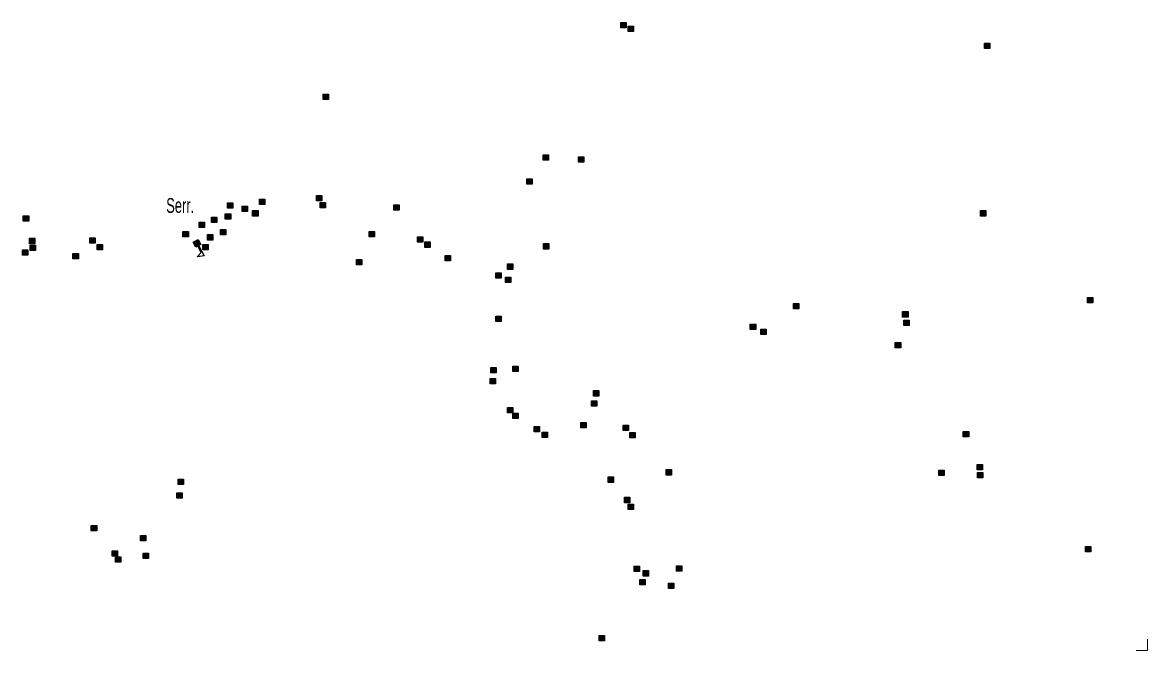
# Model space of a CAD drawing. Extents: x 647.8 to 672.9, y 6929.3 to 6957.3.
# Drawn here: x 666.42 to 672.48, y 6929.25 to 6932.64 of the extents above; entities that cross this region are included whole.
import ezdxf
from ezdxf.enums import TextEntityAlignment as Align

# ---------------------------------------------------------------- set-up
doc = ezdxf.new("R2010")
doc.units = 0
doc.header["$LTSCALE"] = 0.032
for name, color, linetype, lineweight in [('2', 7, 'Continuous', 25), ('4', 7, 'Continuous', 25), ('63', 7, 'Continuous', 13)]:
    doc.layers.add(name, color=color, linetype=linetype, lineweight=lineweight)
doc.layers.add('61', color=7, linetype='Continuous')

msp = doc.modelspace()

# ---------------------------------------------------------------- hatches: boundary and pattern name
at = {"layer": '2'}
for points in [[(669.6418, 6932.6371), (669.6708, 6932.6371), (669.6708, 6932.6081), (669.6418, 6932.6081)], [(669.6813, 6932.6174), (669.7103, 6932.6174), (669.7103, 6932.5884), (669.6813, 6932.5884)], [(671.6009, 6932.5252), (671.6299, 6932.5252), (671.6299, 6932.4962), (671.6009, 6932.4962)], [(668.0381, 6932.251), (668.0671, 6932.251), (668.0671, 6932.222), (668.0381, 6932.222)], [(669.2228, 6931.9241), (669.2518, 6931.9241), (669.2518, 6931.8951), (669.2228, 6931.8951)], [(669.4137, 6931.9131), (669.4427, 6931.9131), (669.4427, 6931.8841), (669.4137, 6931.8841)], [(669.135, 6931.7947), (669.164, 6931.7947), (669.164, 6931.7657), (669.135, 6931.7657)], [(668.003, 6931.7047), (668.032, 6931.7047), (668.032, 6931.6757), (668.003, 6931.6757)], [(667.5226, 6931.6652), (667.5516, 6931.6652), (667.5516, 6931.6362), (667.5226, 6931.6362)], [(667.6015, 6931.6477), (667.6305, 6931.6477), (667.6305, 6931.6187), (667.6015, 6931.6187)], [(667.6959, 6931.685), (667.7249, 6931.685), (667.7249, 6931.656), (667.6959, 6931.656)], [(668.0228, 6931.6674), (668.0518, 6931.6674), (668.0518, 6931.6384), (668.0228, 6931.6384)], [(668.4198, 6931.6543), (668.4488, 6931.6543), (668.4488, 6931.6253), (668.4198, 6931.6253)], [(666.4234, 6931.595), (666.4524, 6931.595), (666.4524, 6931.566), (666.4234, 6931.566)], [(667.437, 6931.5884), (667.466, 6931.5884), (667.466, 6931.5594), (667.437, 6931.5594)], [(667.5116, 6931.606), (667.5406, 6931.606), (667.5406, 6931.577), (667.5116, 6931.577)], [(667.6586, 6931.6235), (667.6876, 6931.6235), (667.6876, 6931.5945), (667.6586, 6931.5945)], [(671.579, 6931.6235), (671.608, 6931.6235), (671.608, 6931.5945), (671.579, 6931.5945)], [(667.2834, 6931.5117), (667.3124, 6931.5117), (667.3124, 6931.4827), (667.2834, 6931.4827)], [(667.3712, 6931.5621), (667.4002, 6931.5621), (667.4002, 6931.5331), (667.3712, 6931.5331)], [(667.485, 6931.5214), (667.514, 6931.5214), (667.514, 6931.4924), (667.485, 6931.4924)], [(668.286, 6931.5117), (668.315, 6931.5117), (668.315, 6931.4827), (668.286, 6931.4827)], [(666.4564, 6931.4744), (666.4854, 6931.4744), (666.4854, 6931.4454), (666.4564, 6931.4454)], [(666.781, 6931.4766), (666.81, 6931.4766), (666.81, 6931.4476), (666.781, 6931.4476)], [(667.4151, 6931.4941), (667.4441, 6931.4941), (667.4441, 6931.4651), (667.4151, 6931.4651)], [(668.5471, 6931.4831), (668.5761, 6931.4831), (668.5761, 6931.4541), (668.5471, 6931.4541)], [(668.5866, 6931.4546), (668.6156, 6931.4546), (668.6156, 6931.4256), (668.5866, 6931.4256)], [(666.4191, 6931.4129), (666.4481, 6931.4129), (666.4481, 6931.3839), (666.4191, 6931.3839)], [(666.4607, 6931.4371), (666.4897, 6931.4371), (666.4897, 6931.4081), (666.4607, 6931.4081)], [(666.6911, 6931.3932), (666.7201, 6931.3932), (666.7201, 6931.3642), (666.6911, 6931.3642)], [(666.8205, 6931.4415), (666.8495, 6931.4415), (666.8495, 6931.4125), (666.8205, 6931.4125)], [(667.3909, 6931.4415), (667.4199, 6931.4415), (667.4199, 6931.4125), (667.3909, 6931.4125)], [(669.225, 6931.4458), (669.254, 6931.4458), (669.254, 6931.4168), (669.225, 6931.4168)], [(668.218, 6931.3603), (668.247, 6931.3603), (668.247, 6931.3313), (668.218, 6931.3313)], [(668.6963, 6931.3822), (668.7253, 6931.3822), (668.7253, 6931.3532), (668.6963, 6931.3532)], [(669.0319, 6931.3361), (669.0609, 6931.3361), (669.0609, 6931.3071), (669.0319, 6931.3071)], [(668.9683, 6931.2879), (668.9973, 6931.2879), (668.9973, 6931.2589), (668.9683, 6931.2589)], [(669.021, 6931.2659), (669.05, 6931.2659), (669.05, 6931.2369), (669.021, 6931.2369)], [(672.156, 6931.1563), (672.185, 6931.1563), (672.185, 6931.1273), (672.156, 6931.1273)], [(670.572, 6931.1233), (670.601, 6931.1233), (670.601, 6931.0943), (670.572, 6931.0943)], [(668.9683, 6931.0553), (668.9973, 6931.0553), (668.9973, 6931.0263), (668.9683, 6931.0263)], [(671.16, 6931.0795), (671.189, 6931.0795), (671.189, 6931.0505), (671.16, 6931.0505)], [(671.1665, 6931.0334), (671.1955, 6931.0334), (671.1955, 6931.0044), (671.1665, 6931.0044)], [(670.3395, 6931.0115), (670.3685, 6931.0115), (670.3685, 6930.9825), (670.3395, 6930.9825)], [(670.3965, 6930.9851), (670.4255, 6930.9851), (670.4255, 6930.9561), (670.3965, 6930.9561)], [(671.1205, 6930.9127), (671.1495, 6930.9127), (671.1495, 6930.8837), (671.1205, 6930.8837)], [(669.0604, 6930.7855), (669.0894, 6930.7855), (669.0894, 6930.7565), (669.0604, 6930.7565)], [(668.942, 6930.7789), (668.971, 6930.7789), (668.971, 6930.7499), (668.942, 6930.7499)], [(668.9376, 6930.7197), (668.9666, 6930.7197), (668.9666, 6930.6907), (668.9376, 6930.6907)], [(669.4948, 6930.6539), (669.5238, 6930.6539), (669.5238, 6930.6249), (669.4948, 6930.6249)], [(669.0319, 6930.5639), (669.0609, 6930.5639), (669.0609, 6930.5349), (669.0319, 6930.5349)], [(669.4839, 6930.599), (669.5129, 6930.599), (669.5129, 6930.57), (669.4839, 6930.57)], [(669.0604, 6930.5332), (669.0894, 6930.5332), (669.0894, 6930.5042), (669.0604, 6930.5042)], [(669.4268, 6930.4827), (669.4558, 6930.4827), (669.4558, 6930.4537), (669.4268, 6930.4537)], [(669.1745, 6930.4608), (669.2035, 6930.4608), (669.2035, 6930.4318), (669.1745, 6930.4318)], [(669.2184, 6930.4301), (669.2474, 6930.4301), (669.2474, 6930.4011), (669.2184, 6930.4011)], [(669.655, 6930.4674), (669.684, 6930.4674), (669.684, 6930.4384), (669.655, 6930.4384)], [(669.6901, 6930.4279), (669.7191, 6930.4279), (669.7191, 6930.3989), (669.6901, 6930.3989)], [(671.4868, 6930.4345), (671.5158, 6930.4345), (671.5158, 6930.4055), (671.4868, 6930.4055)], [(671.5614, 6930.2568), (671.5904, 6930.2568), (671.5904, 6930.2278), (671.5614, 6930.2278)], [(667.2571, 6930.1778), (667.2861, 6930.1778), (667.2861, 6930.1488), (667.2571, 6930.1488)], [(669.5738, 6930.1888), (669.6028, 6930.1888), (669.6028, 6930.1598), (669.5738, 6930.1598)], [(669.8853, 6930.2283), (669.9143, 6930.2283), (669.9143, 6930.1993), (669.8853, 6930.1993)], [(671.3552, 6930.2261), (671.3842, 6930.2261), (671.3842, 6930.1971), (671.3552, 6930.1971)], [(671.5636, 6930.2129), (671.5926, 6930.2129), (671.5926, 6930.1839), (671.5636, 6930.1839)], [(667.2505, 6930.1032), (667.2795, 6930.1032), (667.2795, 6930.0742), (667.2505, 6930.0742)], [(669.6616, 6930.0791), (669.6906, 6930.0791), (669.6906, 6930.0501), (669.6616, 6930.0501)], [(669.6813, 6930.0418), (669.7103, 6930.0418), (669.7103, 6930.0128), (669.6813, 6930.0128)], [(666.7898, 6929.9277), (666.8188, 6929.9277), (666.8188, 6929.8987), (666.7898, 6929.8987)], [(667.0553, 6929.8729), (667.0843, 6929.8729), (667.0843, 6929.8439), (667.0553, 6929.8439)], [(672.145, 6929.8136), (672.174, 6929.8136), (672.174, 6929.7846), (672.145, 6929.7846)], [(666.9017, 6929.7917), (666.9307, 6929.7917), (666.9307, 6929.7627), (666.9017, 6929.7627)], [(666.9193, 6929.7588), (666.9483, 6929.7588), (666.9483, 6929.7298), (666.9193, 6929.7298)], [(667.0684, 6929.7785), (667.0974, 6929.7785), (667.0974, 6929.7495), (667.0684, 6929.7495)], [(669.7142, 6929.7083), (669.7432, 6929.7083), (669.7432, 6929.6793), (669.7142, 6929.6793)], [(669.9424, 6929.7105), (669.9714, 6929.7105), (669.9714, 6929.6815), (669.9424, 6929.6815)], [(669.7449, 6929.6359), (669.7739, 6929.6359), (669.7739, 6929.6069), (669.7449, 6929.6069)], [(669.7625, 6929.6842), (669.7915, 6929.6842), (669.7915, 6929.6552), (669.7625, 6929.6552)], [(669.8985, 6929.6162), (669.9275, 6929.6162), (669.9275, 6929.5872), (669.8985, 6929.5872)], [(669.5255, 6929.3354), (669.5545, 6929.3354), (669.5545, 6929.3064), (669.5255, 6929.3064)]]:
    msp.add_hatch(color=256, dxfattribs=at).paths.add_polyline_path(points)
at = {"layer": '4'}
msp.add_hatch(color=256, dxfattribs=at).paths.add_polyline_path([(667.3659, 6931.4672), (667.3796, 6931.4405), (667.3528, 6931.4269), (667.3392, 6931.4536)])

# ---------------------------------------------------------------- linework, layer by layer
at = {"layer": '2'}
for points in [[(669.6418, 6932.6371), (669.6708, 6932.6371), (669.6708, 6932.6081), (669.6418, 6932.6081)], [(669.6813, 6932.6174), (669.7103, 6932.6174), (669.7103, 6932.5884), (669.6813, 6932.5884)], [(671.6009, 6932.5252), (671.6299, 6932.5252), (671.6299, 6932.4962), (671.6009, 6932.4962)], [(668.0381, 6932.251), (668.0671, 6932.251), (668.0671, 6932.222), (668.0381, 6932.222)], [(669.2228, 6931.9241), (669.2518, 6931.9241), (669.2518, 6931.8951), (669.2228, 6931.8951)], [(669.4137, 6931.9131), (669.4427, 6931.9131), (669.4427, 6931.8841), (669.4137, 6931.8841)], [(669.135, 6931.7947), (669.164, 6931.7947), (669.164, 6931.7657), (669.135, 6931.7657)], [(668.003, 6931.7047), (668.032, 6931.7047), (668.032, 6931.6757), (668.003, 6931.6757)], [(667.5226, 6931.6652), (667.5516, 6931.6652), (667.5516, 6931.6362), (667.5226, 6931.6362)], [(667.6015, 6931.6477), (667.6305, 6931.6477), (667.6305, 6931.6187), (667.6015, 6931.6187)], [(667.6959, 6931.685), (667.7249, 6931.685), (667.7249, 6931.656), (667.6959, 6931.656)], [(668.0228, 6931.6674), (668.0518, 6931.6674), (668.0518, 6931.6384), (668.0228, 6931.6384)], [(668.4198, 6931.6543), (668.4488, 6931.6543), (668.4488, 6931.6253), (668.4198, 6931.6253)], [(666.4234, 6931.595), (666.4524, 6931.595), (666.4524, 6931.566), (666.4234, 6931.566)], [(667.437, 6931.5884), (667.466, 6931.5884), (667.466, 6931.5594), (667.437, 6931.5594)], [(667.5116, 6931.606), (667.5406, 6931.606), (667.5406, 6931.577), (667.5116, 6931.577)], [(667.6586, 6931.6235), (667.6876, 6931.6235), (667.6876, 6931.5945), (667.6586, 6931.5945)], [(671.579, 6931.6235), (671.608, 6931.6235), (671.608, 6931.5945), (671.579, 6931.5945)], [(667.2834, 6931.5117), (667.3124, 6931.5117), (667.3124, 6931.4827), (667.2834, 6931.4827)], [(667.3712, 6931.5621), (667.4002, 6931.5621), (667.4002, 6931.5331), (667.3712, 6931.5331)], [(667.485, 6931.5214), (667.514, 6931.5214), (667.514, 6931.4924), (667.485, 6931.4924)], [(668.286, 6931.5117), (668.315, 6931.5117), (668.315, 6931.4827), (668.286, 6931.4827)], [(666.4564, 6931.4744), (666.4854, 6931.4744), (666.4854, 6931.4454), (666.4564, 6931.4454)], [(666.781, 6931.4766), (666.81, 6931.4766), (666.81, 6931.4476), (666.781, 6931.4476)], [(667.4151, 6931.4941), (667.4441, 6931.4941), (667.4441, 6931.4651), (667.4151, 6931.4651)], [(668.5471, 6931.4831), (668.5761, 6931.4831), (668.5761, 6931.4541), (668.5471, 6931.4541)], [(668.5866, 6931.4546), (668.6156, 6931.4546), (668.6156, 6931.4256), (668.5866, 6931.4256)], [(666.4191, 6931.4129), (666.4481, 6931.4129), (666.4481, 6931.3839), (666.4191, 6931.3839)], [(666.4607, 6931.4371), (666.4897, 6931.4371), (666.4897, 6931.4081), (666.4607, 6931.4081)], [(666.6911, 6931.3932), (666.7201, 6931.3932), (666.7201, 6931.3642), (666.6911, 6931.3642)], [(666.8205, 6931.4415), (666.8495, 6931.4415), (666.8495, 6931.4125), (666.8205, 6931.4125)], [(667.3909, 6931.4415), (667.4199, 6931.4415), (667.4199, 6931.4125), (667.3909, 6931.4125)], [(669.225, 6931.4458), (669.254, 6931.4458), (669.254, 6931.4168), (669.225, 6931.4168)], [(668.218, 6931.3603), (668.247, 6931.3603), (668.247, 6931.3313), (668.218, 6931.3313)], [(668.6963, 6931.3822), (668.7253, 6931.3822), (668.7253, 6931.3532), (668.6963, 6931.3532)], [(669.0319, 6931.3361), (669.0609, 6931.3361), (669.0609, 6931.3071), (669.0319, 6931.3071)], [(668.9683, 6931.2879), (668.9973, 6931.2879), (668.9973, 6931.2589), (668.9683, 6931.2589)], [(669.021, 6931.2659), (669.05, 6931.2659), (669.05, 6931.2369), (669.021, 6931.2369)], [(672.156, 6931.1563), (672.185, 6931.1563), (672.185, 6931.1273), (672.156, 6931.1273)], [(670.572, 6931.1233), (670.601, 6931.1233), (670.601, 6931.0943), (670.572, 6931.0943)], [(668.9683, 6931.0553), (668.9973, 6931.0553), (668.9973, 6931.0263), (668.9683, 6931.0263)], [(671.16, 6931.0795), (671.189, 6931.0795), (671.189, 6931.0505), (671.16, 6931.0505)], [(671.1665, 6931.0334), (671.1955, 6931.0334), (671.1955, 6931.0044), (671.1665, 6931.0044)], [(670.3395, 6931.0115), (670.3685, 6931.0115), (670.3685, 6930.9825), (670.3395, 6930.9825)], [(670.3965, 6930.9851), (670.4255, 6930.9851), (670.4255, 6930.9561), (670.3965, 6930.9561)], [(671.1205, 6930.9127), (671.1495, 6930.9127), (671.1495, 6930.8837), (671.1205, 6930.8837)], [(669.0604, 6930.7855), (669.0894, 6930.7855), (669.0894, 6930.7565), (669.0604, 6930.7565)], [(668.942, 6930.7789), (668.971, 6930.7789), (668.971, 6930.7499), (668.942, 6930.7499)], [(668.9376, 6930.7197), (668.9666, 6930.7197), (668.9666, 6930.6907), (668.9376, 6930.6907)], [(669.4948, 6930.6539), (669.5238, 6930.6539), (669.5238, 6930.6249), (669.4948, 6930.6249)], [(669.0319, 6930.5639), (669.0609, 6930.5639), (669.0609, 6930.5349), (669.0319, 6930.5349)], [(669.4839, 6930.599), (669.5129, 6930.599), (669.5129, 6930.57), (669.4839, 6930.57)], [(669.0604, 6930.5332), (669.0894, 6930.5332), (669.0894, 6930.5042), (669.0604, 6930.5042)], [(669.4268, 6930.4827), (669.4558, 6930.4827), (669.4558, 6930.4537), (669.4268, 6930.4537)], [(669.1745, 6930.4608), (669.2035, 6930.4608), (669.2035, 6930.4318), (669.1745, 6930.4318)], [(669.2184, 6930.4301), (669.2474, 6930.4301), (669.2474, 6930.4011), (669.2184, 6930.4011)], [(669.655, 6930.4674), (669.684, 6930.4674), (669.684, 6930.4384), (669.655, 6930.4384)], [(669.6901, 6930.4279), (669.7191, 6930.4279), (669.7191, 6930.3989), (669.6901, 6930.3989)], [(671.4868, 6930.4345), (671.5158, 6930.4345), (671.5158, 6930.4055), (671.4868, 6930.4055)], [(671.5614, 6930.2568), (671.5904, 6930.2568), (671.5904, 6930.2278), (671.5614, 6930.2278)], [(667.2571, 6930.1778), (667.2861, 6930.1778), (667.2861, 6930.1488), (667.2571, 6930.1488)], [(669.5738, 6930.1888), (669.6028, 6930.1888), (669.6028, 6930.1598), (669.5738, 6930.1598)], [(669.8853, 6930.2283), (669.9143, 6930.2283), (669.9143, 6930.1993), (669.8853, 6930.1993)], [(671.3552, 6930.2261), (671.3842, 6930.2261), (671.3842, 6930.1971), (671.3552, 6930.1971)], [(671.5636, 6930.2129), (671.5926, 6930.2129), (671.5926, 6930.1839), (671.5636, 6930.1839)], [(667.2505, 6930.1032), (667.2795, 6930.1032), (667.2795, 6930.0742), (667.2505, 6930.0742)], [(669.6616, 6930.0791), (669.6906, 6930.0791), (669.6906, 6930.0501), (669.6616, 6930.0501)], [(669.6813, 6930.0418), (669.7103, 6930.0418), (669.7103, 6930.0128), (669.6813, 6930.0128)], [(666.7898, 6929.9277), (666.8188, 6929.9277), (666.8188, 6929.8987), (666.7898, 6929.8987)], [(667.0553, 6929.8729), (667.0843, 6929.8729), (667.0843, 6929.8439), (667.0553, 6929.8439)], [(672.145, 6929.8136), (672.174, 6929.8136), (672.174, 6929.7846), (672.145, 6929.7846)], [(666.9017, 6929.7917), (666.9307, 6929.7917), (666.9307, 6929.7627), (666.9017, 6929.7627)], [(666.9193, 6929.7588), (666.9483, 6929.7588), (666.9483, 6929.7298), (666.9193, 6929.7298)], [(667.0684, 6929.7785), (667.0974, 6929.7785), (667.0974, 6929.7495), (667.0684, 6929.7495)], [(669.7142, 6929.7083), (669.7432, 6929.7083), (669.7432, 6929.6793), (669.7142, 6929.6793)], [(669.9424, 6929.7105), (669.9714, 6929.7105), (669.9714, 6929.6815), (669.9424, 6929.6815)], [(669.7449, 6929.6359), (669.7739, 6929.6359), (669.7739, 6929.6069), (669.7449, 6929.6069)], [(669.7625, 6929.6842), (669.7915, 6929.6842), (669.7915, 6929.6552), (669.7625, 6929.6552)], [(669.8985, 6929.6162), (669.9275, 6929.6162), (669.9275, 6929.5872), (669.8985, 6929.5872)], [(669.5255, 6929.3354), (669.5545, 6929.3354), (669.5545, 6929.3064), (669.5255, 6929.3064)]]:
    msp.add_lwpolyline(points, close=True, dxfattribs=at)
at = {"layer": '4'}
msp.add_line((667.3684, 6931.4348), (667.364, 6931.4326), dxfattribs=at)
for points in [[(667.3659, 6931.4672), (667.3796, 6931.4405), (667.3528, 6931.4269), (667.3392, 6931.4536)], [(667.3684, 6931.4348), (667.3969, 6931.3792), (667.36, 6931.3744), (667.3819, 6931.3974), (667.364, 6931.4326)]]:
    msp.add_lwpolyline(points, close=True, dxfattribs=at)
at = {"layer": '63'}
msp.add_lwpolyline([(672.4172, 6929.2539), (672.4788, 6929.2539), (672.4788, 6929.3146)], dxfattribs=at)

# ---------------------------------------------------------------- texts
at = {"layer": '61', "width": 0.65}
msp.add_text('Serr.', height=0.08, dxfattribs=at).set_placement((667.3439, 6931.6114), align=Align.RIGHT)

doc.saveas('drawing.dxf')
